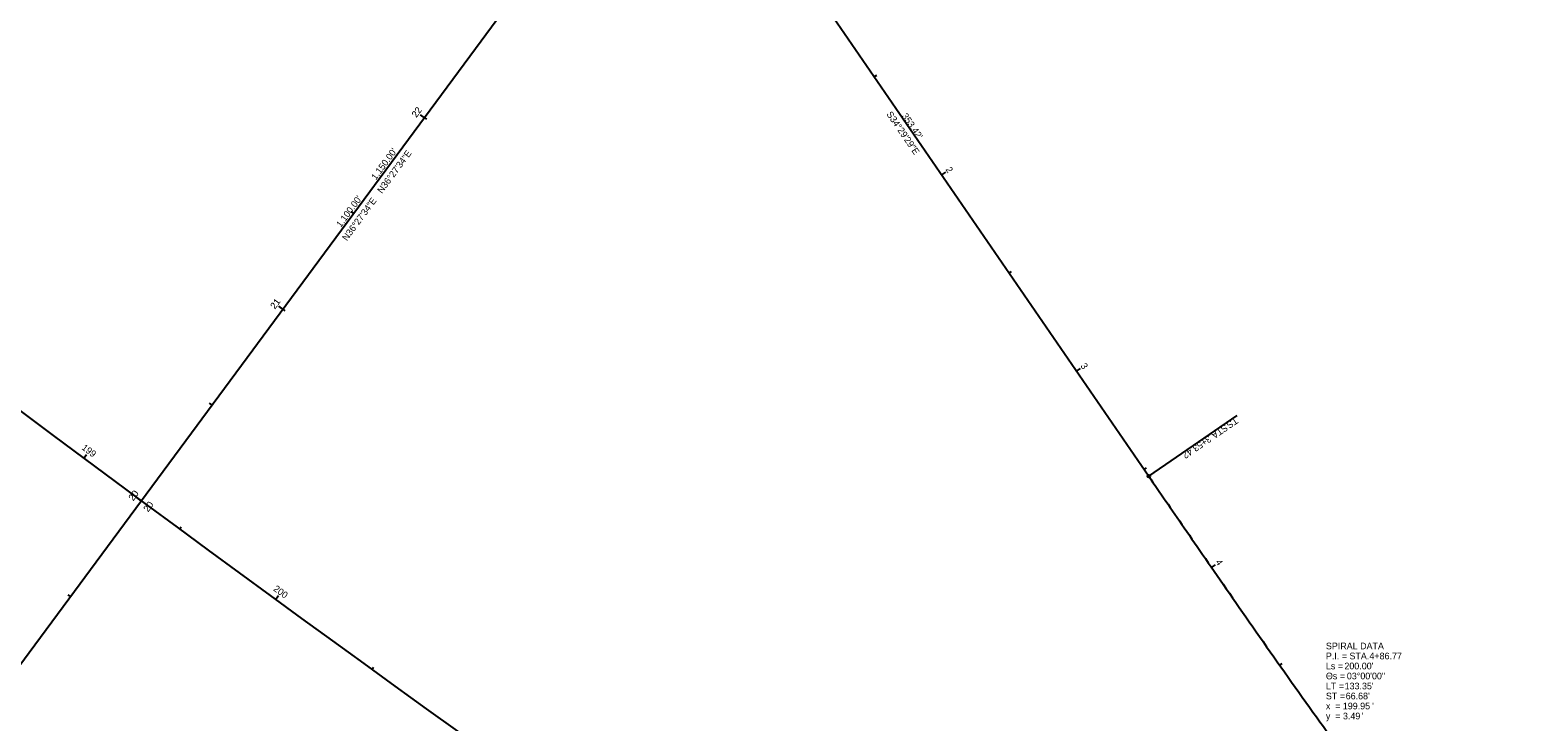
# Model space of a CAD drawing. Extents: x 1323137 to 1326838, y 458936 to 461644.
# Drawn here: x 1325088 to 1325721, y 459962 to 460252 of the extents above; entities that cross this region are included whole.
import ezdxf

# ---------------------------------------------------------------- set-up
doc = ezdxf.new("R2010")
doc.units = 0
for name, color, linetype in [('CM_Corridor_Range_Final', 7, 'Continuous'), ('Default', 7, 'Continuous'), ('DR_P_Ditch', 7, 'Continuous'), ('DT_P_Graded_Shoulder', 7, 'Continuous'), ('MD_P_ACB_B', 7, 'Continuous'), ('MD_P_ACB_T', 7, 'Continuous'), ('MD_P_ACIC_B', 7, 'Continuous'), ('MD_P_ACSC_T', 7, 'Continuous'), ('MD_P_AGB_T', 7, 'Continuous'), ('PV_P_Shoulder', 7, 'Continuous'), ('RD_P_GR_Rt', 7, 'Continuous'), ('SG_P_Conduit', 7, 'Continuous'), ('SG_P_Mast_Arm', 7, 'Continuous'), ('SG_P_Wiring', 7, 'Continuous'), ('SN_P_Signs', 7, 'Continuous'), ('SN_X_Public', 7, 'Continuous'), ('UT_X_Electric_Cells', 7, 'Continuous')]:
    doc.layers.add(name, color=color, linetype=linetype)

msp = doc.modelspace()

# ---------------------------------------------------------------- linework, layer by layer
at = {"layer": 'CM_Corridor_Range_Final'}
for p, q in [((1325253.87, 460215.27), (1325252.26, 460216.46)), ((1325224.16, 460175.05), (1325223.2, 460175.77)), ((1325194.45, 460134.84), (1325192.84, 460136.03)), ((1325164.74, 460094.63), (1325163.77, 460095.34)), ((1325110.92, 460072.27), (1325112.11, 460073.87)), ((1325135.02, 460054.41), (1325133.41, 460055.6)), ((1325151.12, 460042.54), (1325151.83, 460043.51)), ((1325105.31, 460014.2), (1325104.34, 460014.91)), ((1325191.44, 460012.98), (1325192.62, 460014.59)), ((1325231.88, 459983.57), (1325232.59, 459984.55))]:
    msp.add_line(p, q, dxfattribs=at)
at = {"layer": 'Default'}
msp.add_arc((1332431.06, 469929.07), 12277.67, 232.043309, 236.873031, dxfattribs=at)
msp.add_open_spline([(1325558, 460064.72), (1325562.72, 460057.86), (1325572.16, 460044.12), (1325591.08, 460016.68), (1325614.9, 459982.49), (1325639.17, 459948.61), (1325658.98, 459921.81), (1325669.03, 459908.51), (1325674.1, 459901.9)], degree=3, dxfattribs=at)
at = {"layer": 'MD_P_ACB_B'}
msp.add_line((1325558, 460064.72), (1325595.09, 460090.21), dxfattribs=at)
msp.add_circle((1325558, 460064.72), 0.6, dxfattribs=at)
at = {"layer": 'PV_P_Shoulder'}
for p, q in [((1325253.87, 460215.27), (1325254.84, 460214.55)), ((1325194.45, 460134.84), (1325195.41, 460134.13)), ((1325135.02, 460054.41), (1325136.63, 460053.22))]:
    msp.add_line(p, q, dxfattribs=at)
at = {"layer": 'SG_P_Conduit'}
for p, q in [((1324897.32, 459732.7), (1325580.71, 460657.62)), ((1325357.87, 460356.02), (1325558, 460064.72))]:
    msp.add_line(p, q, dxfattribs=at)
msp.add_open_spline([(1325558, 460064.72), (1325562.72, 460057.86), (1325572.16, 460044.12), (1325591.08, 460016.68), (1325614.9, 459982.49), (1325639.17, 459948.61), (1325658.98, 459921.81), (1325669.03, 459908.51), (1325674.1, 459901.9)], degree=3, dxfattribs=at)
at = {"layer": 'SG_P_Mast_Arm'}
for p, q in [((1325442.81, 460232.38), (1325443.8, 460233.06)), ((1325253.87, 460215.27), (1325252.26, 460216.46)), ((1325471.12, 460191.17), (1325472.77, 460192.31)), ((1325224.16, 460175.05), (1325223.2, 460175.77)), ((1325499.44, 460149.96), (1325500.43, 460150.64)), ((1325194.45, 460134.84), (1325192.84, 460136.03)), ((1325527.75, 460108.75), (1325529.4, 460109.89)), ((1325164.74, 460094.63), (1325163.77, 460095.34)), ((1325556.07, 460067.54), (1325557.06, 460068.22)), ((1325135.02, 460054.41), (1325133.41, 460055.6)), ((1325584.42, 460026.36), (1325586.06, 460027.49)), ((1325105.31, 460014.2), (1325104.34, 460014.91)), ((1325613.02, 459985.35), (1325614, 459986.04))]:
    msp.add_line(p, q, dxfattribs=at)
at = {"layer": 'SN_P_Signs'}
for p, q in [((1324897.32, 459732.7), (1325551, 460617.41)), ((1325357.87, 460356.02), (1325558, 460064.72))]:
    msp.add_line(p, q, dxfattribs=at)
msp.add_arc((1332431.06, 469929.07), 12277.67, 232.043309, 236.873031, dxfattribs=at)
msp.add_open_spline([(1325558, 460064.72), (1325562.72, 460057.86), (1325572.16, 460044.12), (1325591.08, 460016.68), (1325614.9, 459982.49), (1325639.17, 459948.61), (1325658.98, 459921.81), (1325669.03, 459908.51), (1325674.1, 459901.9)], degree=3, dxfattribs=at)
at = {"layer": 'SN_X_Public'}
for p, q in [((1325253.87, 460215.27), (1325252.91, 460215.98)), ((1325194.45, 460134.84), (1325193.48, 460135.55)), ((1325110.92, 460072.27), (1325111.63, 460073.23)), ((1325135.02, 460054.41), (1325133.41, 460055.6)), ((1325191.44, 460012.98), (1325192.62, 460014.59))]:
    msp.add_line(p, q, dxfattribs=at)

# ---------------------------------------------------------------- texts
at = {"layer": 'CM_Corridor_Range_Final'}
for s, rotation, p in [('22', 53.54061, (1325250.62, 460215.07)), ('21', 53.54061, (1325191.19, 460134.63)), ('199', 323.40061, (1325109.82, 460076.2)), ('20', 53.54061, (1325131.73, 460054.17)), ('200', 323.86728, (1325190.28, 460016.92))]:
    msp.add_text(s, height=2.8, rotation=rotation, dxfattribs=at).set_placement(p)
at = {"layer": 'DR_P_Ditch'}
msp.add_text("1,100.00'", height=2.8, rotation=53.54061, dxfattribs=at).set_placement((1325218.85, 460168.91))
at = {"layer": 'DT_P_Graded_Shoulder'}
for s, rotation, p in [('S34°29\'29"E', 304.49136, (1325447.78, 460216.67)), ('N36°27\'34"E', 53.54061, (1325236.12, 460183.17))]:
    msp.add_text(s, height=2.8, rotation=rotation, dxfattribs=at).set_placement(p)
at = {"layer": 'MD_P_ACB_B'}
for s, p in [('TS', (1325594.27, 460089.59)), (' STA. ', (1325590.85, 460087.24)), ('3+53.42', (1325583.06, 460081.89))]:
    msp.add_text(s, height=2.8, rotation=214.49136, dxfattribs=at).set_placement(p)
at = {"layer": 'MD_P_ACB_T'}
for s, rotation, p in [("353.42'", 304.49136, (1325454.19, 460215.9)), ("1,150.00'", 53.54061, (1325233.56, 460188.82))]:
    msp.add_text(s, height=2.8, rotation=rotation, dxfattribs=at).set_placement(p)
at = {"layer": 'MD_P_ACIC_B'}
msp.add_text('N36°27\'34"E', height=2.8, rotation=53.54061, dxfattribs=at).set_placement((1325236.12, 460183.17))
at = {"layer": 'MD_P_ACSC_T'}
msp.add_text("1,150.00'", height=2.8, rotation=53.54061, dxfattribs=at).set_placement((1325233.56, 460188.82))
at = {"layer": 'MD_P_AGB_T'}
for s, p in [('SPIRAL DATA', (1325632.39, 459992.05)), ('P.I. = STA. ', (1325632.39, 459987.85)), ('4+86.77', (1325650.66, 459987.85)), ('Θs = ', (1325632.39, 459979.45)), ('Ls = ', (1325632.39, 459983.65)), ("200.00'", (1325640.15, 459983.65)), ('03°00\'00"', (1325641.19, 459979.45)), ('LT = ', (1325632.39, 459975.25)), ("133.35'", (1325640.24, 459975.25)), ('x  = ', (1325632.39, 459966.85)), ('ST = ', (1325632.39, 459971.05)), ('199.95', (1325639.49, 459966.85)), ("66.68'", (1325640.7, 459971.05)), ("'", (1325651.78, 459966.85)), ('y  = ', (1325632.39, 459962.65)), ('3.49', (1325639.55, 459962.65)), ("'", (1325647.37, 459962.65))]:
    msp.add_text(s, height=2.8, dxfattribs=at).set_placement(p)
at = {"layer": 'PV_P_Shoulder'}
msp.add_text('20', height=2.8, rotation=53.54061, dxfattribs=at).set_placement((1325137.96, 460049.47))
at = {"layer": 'RD_P_GR_Rt'}
msp.add_text('N36°27\'34"E', height=2.8, rotation=53.54061, dxfattribs=at).set_placement((1325221.41, 460163.26))
at = {"layer": 'SG_P_Mast_Arm'}
for s, rotation, p in [('22', 53.54061, (1325250.58, 460215.01)), ('2', 304.49136, (1325472.59, 460193.45)), ('21', 53.54061, (1325191.23, 460134.69)), ('3', 304.49136, (1325529.23, 460111.02)), ('20', 53.54061, (1325131.69, 460054.1)), ('4', 304.65409, (1325585.88, 460028.63))]:
    msp.add_text(s, height=2.8, rotation=rotation, dxfattribs=at).set_placement(p)
at = {"layer": 'SG_P_Wiring'}
msp.add_text('N36°27\'34"E', height=2.8, rotation=53.54061, dxfattribs=at).set_placement((1325221.41, 460163.26))
at = {"layer": 'SN_X_Public'}
for s, rotation, p in [('20', 53.54061, (1325131.73, 460054.17)), ('200', 323.86728, (1325190.28, 460016.92))]:
    msp.add_text(s, height=2.8, rotation=rotation, dxfattribs=at).set_placement(p)
at = {"layer": 'UT_X_Electric_Cells'}
msp.add_text("1,100.00'", height=2.8, rotation=53.54061, dxfattribs=at).set_placement((1325218.85, 460168.91))

doc.saveas('drawing.dxf')
